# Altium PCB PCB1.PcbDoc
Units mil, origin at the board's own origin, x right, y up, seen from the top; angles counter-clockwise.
Board outline 3910.03 x 3525.03 mil, 2 copper layers (Top Layer, Bottom Layer); 80 components, 69 nets, 260 pads, 105 vias.
Unrouted connection lines stored in the file: 3.
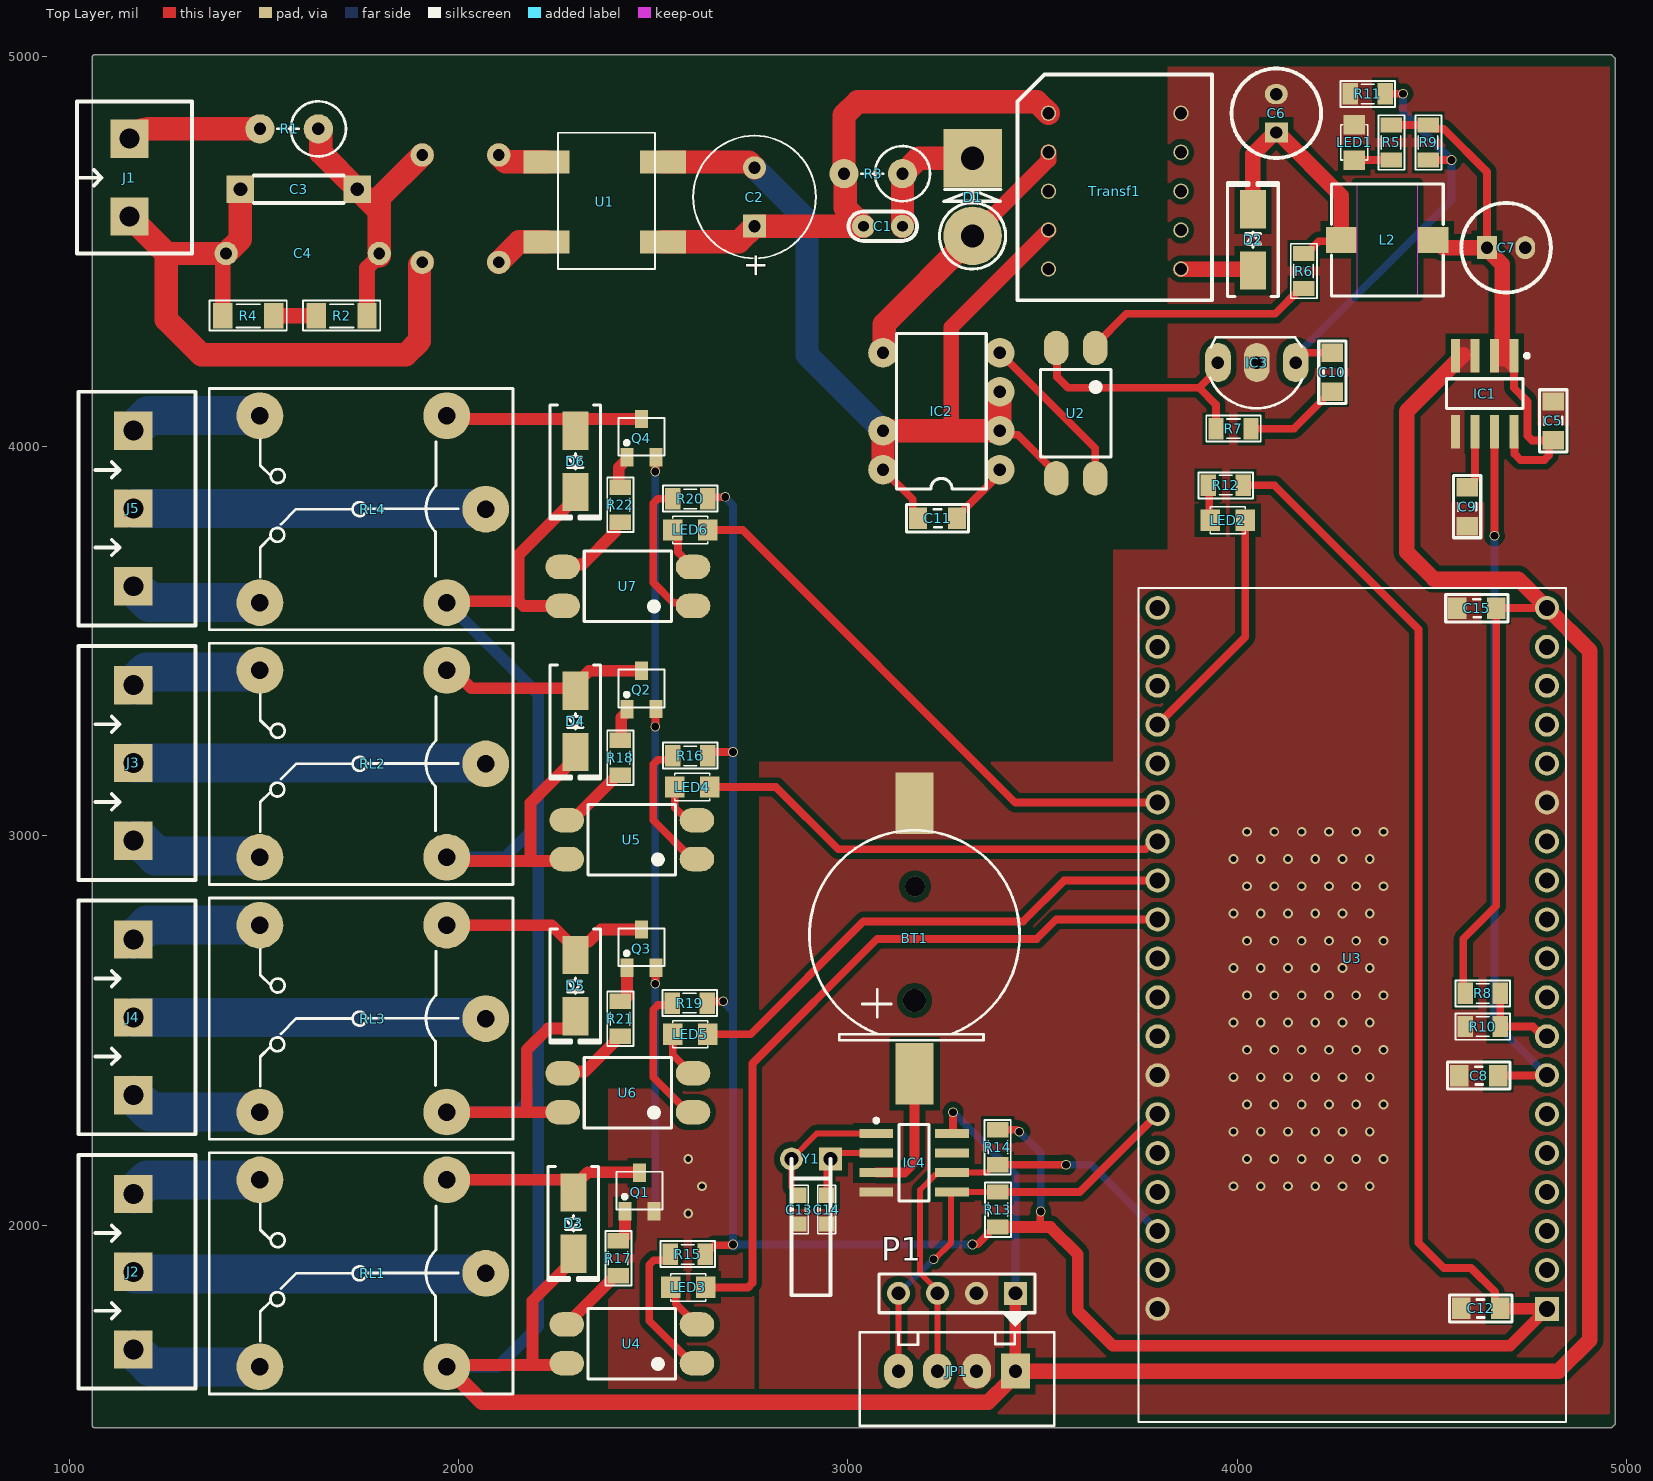
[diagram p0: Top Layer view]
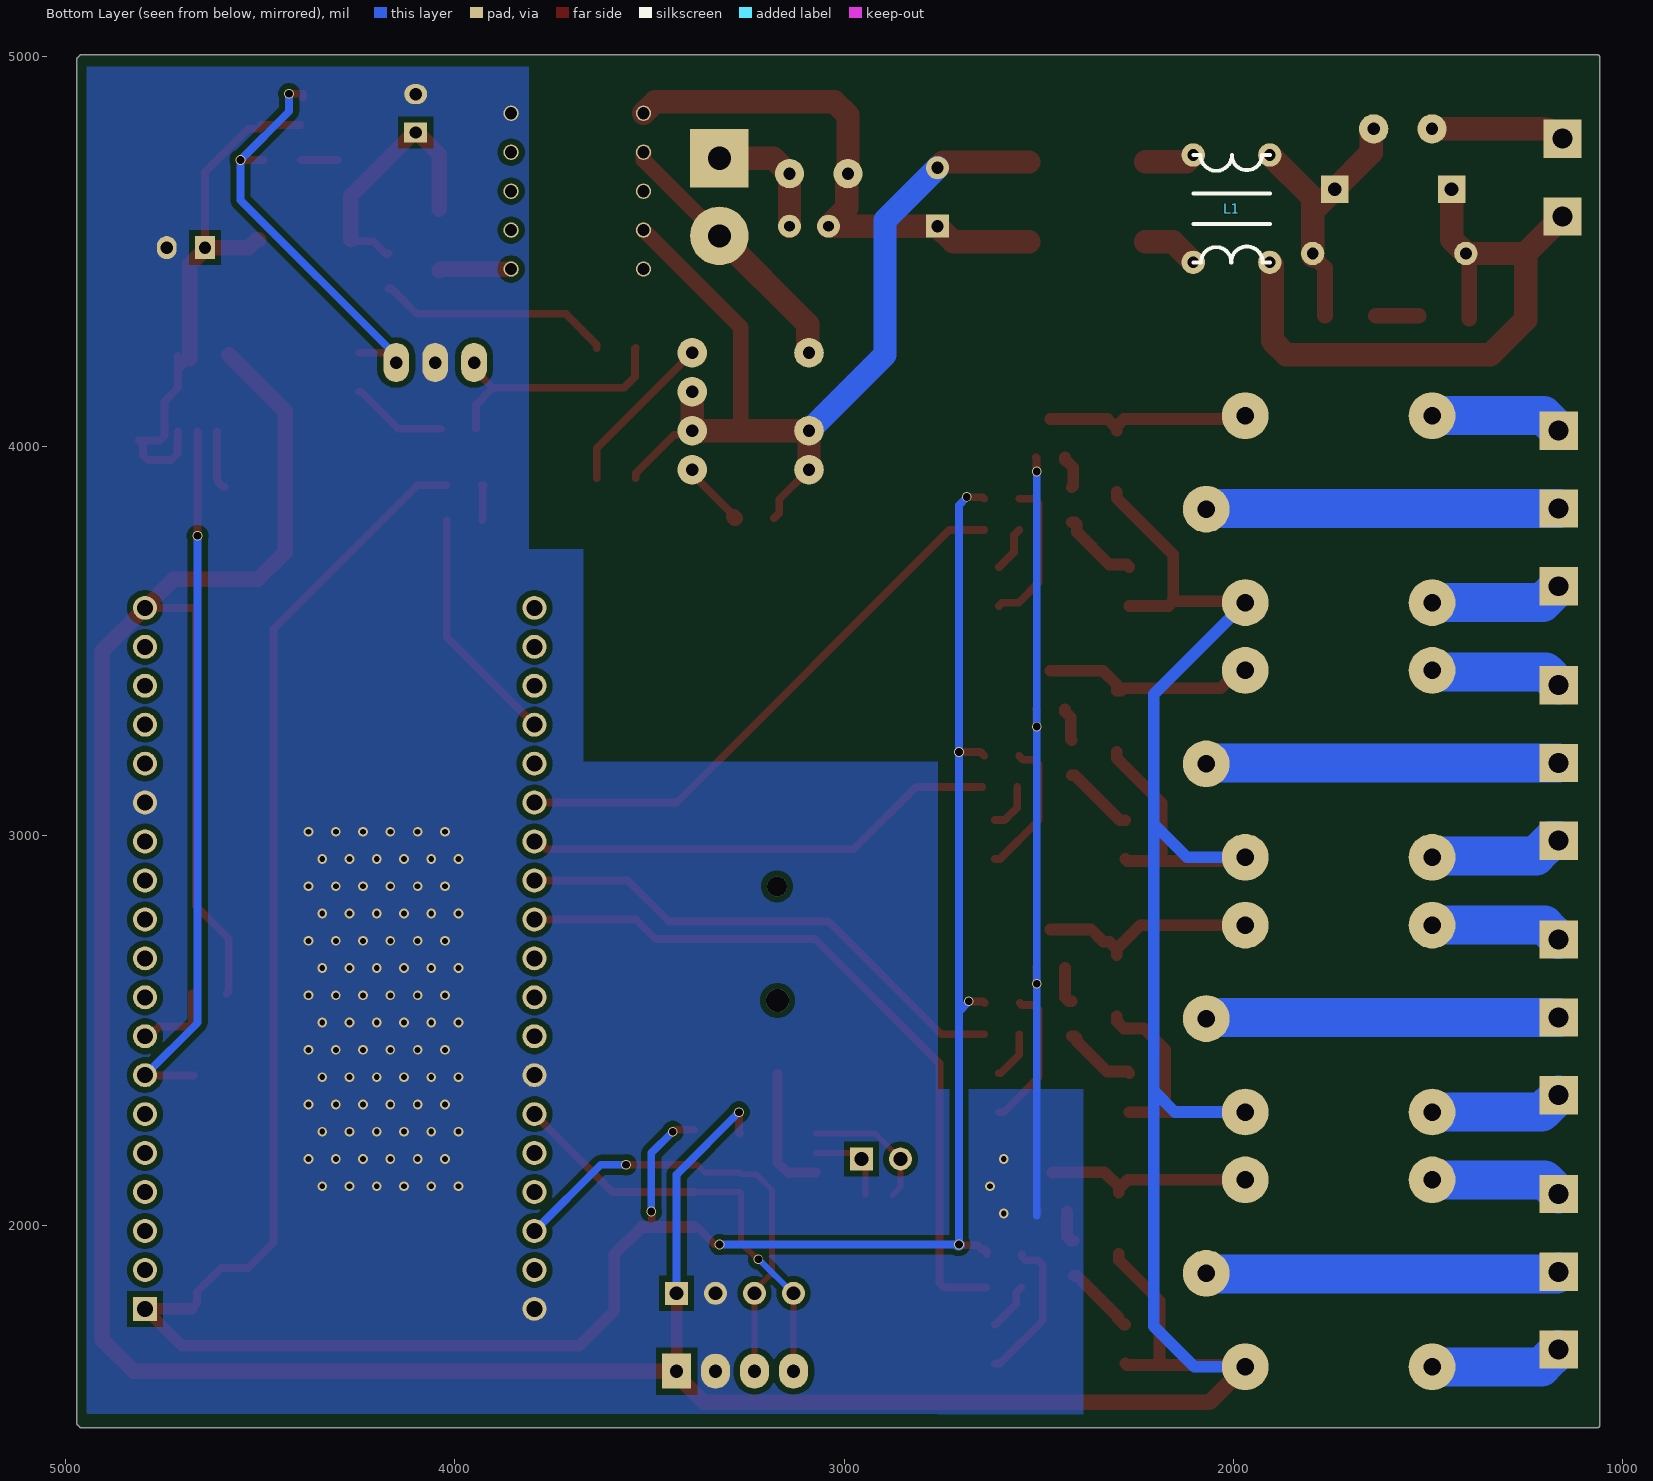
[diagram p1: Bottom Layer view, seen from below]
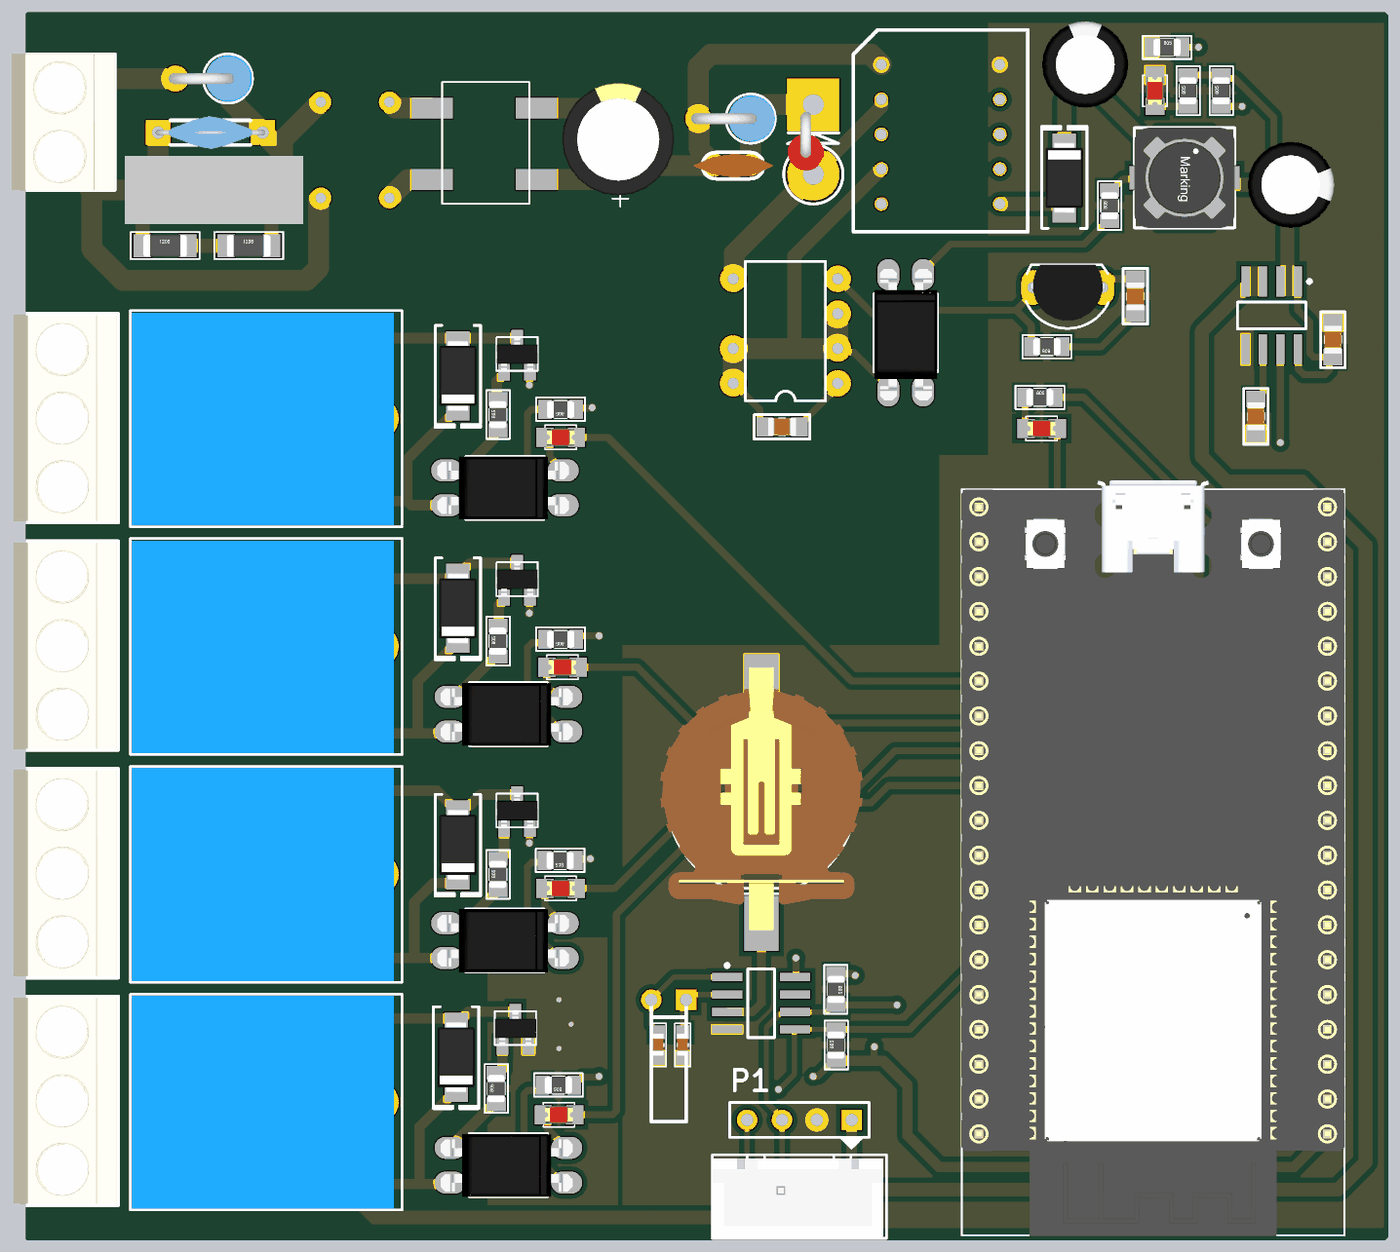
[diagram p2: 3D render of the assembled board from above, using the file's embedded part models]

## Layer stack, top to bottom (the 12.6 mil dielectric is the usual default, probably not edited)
Top Solder: solder mask 0.4, Solder Resist, Dk 3.5
Top Layer: signal copper 1.4
Dielectric 1: dielectric 12.6, FR-4, Dk 4.8
Bottom Layer: signal copper 1.4
Bottom Solder: solder mask 0.4, Solder Resist, Dk 3.5

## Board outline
1059.98,1485 1059.98,5000 cw(c1065,5000) 1061.45,5003.55 cw(c1065,5000) 1065.03,5005.01 4959.14,5005.01 cw(c4959.14,5000) 4962.71,5003.53 4968.55,4997.69 cw(c4965.03,4994.15) 4970.02,4994.14 4970.02,1490.86 cw(c4965,1490.86) 4968.53,1487.29 4962.69,1481.45 cw(c4959.15,1484.97) 4959.14,1479.98 1065,1479.98 cw(c1065,1485)

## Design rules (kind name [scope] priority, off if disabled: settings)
Clearance [All] p1: gap=15 ignorepadtopadclearanceinfootprint=FALSE
PolygonConnect [All] p1: connectstyle=Direct reliefconductorwidth=10 reliefentries=4 polygonreliefangle="90 Angle" airgapwidth=10
RoutingVias [All] p1: holewidth=18 width=23 viastyle="Through Hole" minholewidth=15 minwidth=20 maxholewidth=40 maxwidth=50
SolderMaskExpansion [All] p1: expansion=4 istentingtop=FALSE
Width [All] p1: maxlimit=100 minlimit=12 preferedwidth=15
30 further rules are at their usual default settings.

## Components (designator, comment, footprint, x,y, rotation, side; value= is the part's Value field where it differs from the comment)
BT1 "Battery3.3V" "CR1220 SMD" 3180,2730 r0 top
C1 "10nF/500V" "tu gom" 3090,4565 r0 top
C2 "33uF" CA-ALU-8 2760,4640 r90 top value=104
C3 "14D471K" 103/2KV 1440,4660 r0 top
C4 "Cap AC filter" "Cap AC filter" 1600,4495 r0 top
C5 "100nF" CAP_0805 4810,4065 r90 top value=33p
C6 "330uF/16V" C8mm 4100,4855 r90 top
C7 "100uF" C8mm 4690,4510 r0 top
C8 "100nF" CAP_0805 4620,2385 r0 top value=33p
C9 "10nF" CAP_0805 4591,3845 r270 top value=33p
C10 "100nF" CAP_0805 4245,4190 r270 top value=33p
C11 "100nF" CAP_0805 3230,3816 r0 top value=33p
C12 "100nF" CAP_0805 4625,1785 r180 top value=33p
C13 "10pF" CAP_0603 2875,2040 r90 top value=33p
C14 "10pF" CAP_0603 2945,2040 r90 top value=33p
C15 "100nF" CAP_0805 4615,3585 r0 top value=33p
D1 "1N4937" D5AN 3320,4740 r270 top value=1N5408
D2 "SS34" "DIODE SMA" 4040,4530 r90 top
D3 "M7" "DIODE SMA" 2295,2005 r270 top
D4 "M7" "DIODE SMA" 2300,3293.74 r270 top
D5 "M7" "DIODE SMA" 2300,2615 r270 top
D6 "M7" "DIODE SMA" 2300,3961.26 r270 top
IC1 "Current Sensor IC" SOIC-8 4635,4135 r270 top
IC2 "TNY267" TNY264 3436.85,3873.46 r90 top
IC3 "TL431" qto-92 4050,4215 r180 top
IC4 "DS1307Z" SOIC-8 3170,2160 r0 top
J1 "KF2" KF2-5.08 1155,4690 r90 top
J2 "KF3" KF3-5.08 1165,2080 r270 top
J3 "KF3" KF3-5.08 1165,3386.67 r270 top
J4 "KF3" KF3-5.08 1165,2733.33 r270 top
J5 "KF3" KF3-5.08 1165,4040 r270 top
JP1 "JP4" CON4 3430,1625 r180 top value="Connector 4"
L1 "Inductor EE8.3" "Inductor EE8.3" 2005,4610 r270 bottom
L2 "3.3uH" L-SMD-M-7.3x4.5 4385,4530 r90 top value="150 mH"
LED1 "LED" LED-0805-Red 4300,4735 r90 top value="LED 3 ly Single Colour"
LED2 "LED" LED-0805-Red 3930,3810 r0 top value="LED 3 ly Single Colour"
LED3 "LED" LED-0805-Red 2545,1840 r0 top value="LED 3 ly Single Colour"
LED4 "LED" LED-0805-Red 2555,3125 r0 top value="LED 3 ly Single Colour"
LED5 "LED" LED-0805-Red 2550,2490 r0 top value="LED 3 ly Single Colour"
LED6 "LED" LED-0805-Red 2550,3785 r0 top value="LED 3 ly Single Colour"
P1 "Header 4" HDR1X4 3430,1825 r180 top
Q1 "2N222" SOT23D 2465,2085 r0 top value=C1815
Q2 "2N222" SOT23D 2470,3374.21 r0 top value=C1815
Q3 "2N222" SOT23D 2470,2710 r0 top value=C1815
Q4 "2N222" SOT23D 2470,4020.79 r0 top value=C1815
R1 "2R/2W" RES-1WD 1575,4815 r180 top value="R1/4W - 1K"
R2 "1M" RES-SMD-1206 1700,4335 r0 top
R3 "200k/2W" RES-1WD 3075,4700 r180 top value="R1/4W - 1K"
R4 "1M" RES-SMD-1206 1460,4335 r0 top
R5 "1k" RES-SMD-0805 4395,4780 r90 top
R6 "200R" RES-SMD-0805 4170,4450 r90 top
R7 "3.3k" RES-SMD-0805 3990,4045 r180 top
R8 "10k" RES-SMD-0805 4630,2595 r0 top
R9 "11k" RES-SMD-0805 4490,4780 r90 top
R10 "3k" RES-SMD-0805 4630,2510 r0 top
R11 "10k" RES-SMD-0805 4335,4905 r0 top
R12 "1k" RES-SMD-0805 3970,3900 r0 top
R13 "10k" RES-SMD-0805 3385,2040 r90 top
R14 "10k" RES-SMD-0805 3385,2200 r270 top
R15 "1k" RES-SMD-0805 2588.5,1925 r180 top
R16 "1k" RES-SMD-0805 2595,3205 r180 top
R17 "1k" RES-SMD-0805 2410,1915 r90 top
R18 "1k" RES-SMD-0805 2415,3200 r90 top
R19 "1k" RES-SMD-0805 2593.5,2570 r180 top
R20 "1k" RES-SMD-0805 2595,3865 r180 top
R21 "1k" RES-SMD-0805 2415,2530 r90 top
R22 "1k" RES-SMD-0805 2415,3850 r90 top
RL1 "Relay 10A/12V" "RELAY 5" 1745,1876.17 r180 top value="Relay SPDT, 10A, 12V"
RL2 "Relay 10A/12V" "RELAY 5" 1745,3184.39 r180 top value="Relay SPDT, 10A, 12V"
RL3 "Relay 10A/12V" "RELAY 5" 1745,2530.28 r180 top value="Relay SPDT, 10A, 12V"
RL4 "Relay 10A/12V" "RELAY 5" 1745,3838.5 r180 top value="Relay SPDT, 10A, 12V"
Transf1 "Transformer EE12.7" "Transformer EE12.7" 3685,4655 r270 top
U1 "Diode Bridge Flate" DB207S 2375,4625 r270 top
U2 "OPTO PC817 SMD" SOP4 3585,4085 r270 top value=PC817
U3 "ESP32-DEVKITC-32D" MODULE_ESP32-DEVKITC-32D 4295,2562.95 r180 top
U4 "OPTO PC817 SMD" SOP4 2445,1695 r180 top value=PC817
U5 "OPTO PC817 SMD" SOP4 2445,2990 r180 top value=PC817
U6 "OPTO PC817 SMD" SOP4 2435,2340 r180 top value=PC817
U7 "OPTO PC817 SMD" SOP4 2435,3640 r180 top value=PC817
Y1 "32.768KHz" XTAL32K 2955,2170 r180 top

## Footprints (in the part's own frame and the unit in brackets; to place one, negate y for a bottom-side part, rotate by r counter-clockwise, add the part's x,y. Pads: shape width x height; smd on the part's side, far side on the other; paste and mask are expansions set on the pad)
103/2KV [mm]
  rect 1.8x1.8 hole 0.9: 1(0,0) 2(7.62,0)
  silkscreen extent 0.89,-0.89 6.73,0.89, body extent -0.19,-1.2 7.81,1.19, height 9.03
C8mm [mm]
  rect 1.3x1.5 hole 0.8: 1(-1.25,0)
  oval 1.3x1.5 hole 0.8: 2(1.25,0)
  silkscreen extent -2.92,-2.92 2.92,2.92, body extent -3.15,-3.15 3.16,3.15, height 11.51
CA-ALU-8 [mm] "Polarized capacitors, Aluminum Electrolytic Capacitors, 2-Leads, Body 8x16x3.5x0.5"
  rect 1.5x1.5 hole 0.8: 1(-1.905,0)
  round 1.5 hole 0.8: 2(1.905,0)
  silkscreen extent -4,-4 4,4, body extent -4.1,-4.1 4.1,4.1, height 14.4
"Cap AC filter" [mil]
  round 60 hole 30: 1(-196.85,0) 2(196.85,0)
  body extent -256,-98 256,98, height 472
CAP_0603 [mm]
  rect 1x0.95 smd mask+0.076: 1(-0.94,0) 2(0.94,0)
  silkscreen extent -1.57,-0.58 1.57,0.58, body extent -0.77,-0.39 0.83,0.41, height 0.9
CAP_0805 [mm]
  rect 1.2x1.4 smd: 1(-1.27,-0.025) 2(1.27,-0.025)
  silkscreen extent -2.03,-0.91 2.03,0.86, body extent -1.01,-0.66 1.01,0.61, height 0.61
CON4 [mil] "CON4"
  rect 75x90 hole 34: 1(0,0)
  oval 75x90 hole 34: 2(100,0) 3(200,0) 4(300,0)
  silkscreen extent -100,-150 400,140, body extent -90,-90 398,136, height 276
"CR1220 SMD" [mil] "CR1220 SMD"
  rect 98.43x157.48 smd: 1(-9,-341) 2(-9,353)
  silkscreen extent -279,-255 261,284, body extent -299,-362 281,394, height 179
D5AN [mil] "Diode 5A, W 200mil, L 250mil"
  round 150 hole 60: 1(200,0)
  rect 150x150 hole 60: 2(0,0)
  silkscreen extent 81,-85 285,85, body extent 21,-74 189,31, height 252
DB207S [mm] "Bridge Rectifiers 2A 1000V"
  rect 1.5x3 smd: 1(2.54,3.81) 2(2.54,-3.785) 3(-2.667,-3.785) 4(-2.667,3.81)
  silkscreen extent -4.57,-3.05 4.32,3.3
"DIODE SMA" [mm] "SMA"
  rect 2.5x1.7 smd: 1(-2,0) 2(2,0)
  silkscreen extent -3.68,-1.65 3.75,1.65, body extent -2.6,-1.37 2.6,1.37, height 2.4
HDR1X4 [mm] "Connector; Header; 4 Position"
  rect 1.5x1.5 hole 0.9: 1(0,0)
  round 1.5 hole 0.9: 2(2.54,0) 3(5.08,0) 4(7.62,0)
  silkscreen extent -1.27,-1.27 8.89,1.27
"Inductor EE8.3" [mil]
  round 60 hole 30: 1(-137.8,98.43) 2(-137.8,-98.43) 3(137.8,98.43) 4(137.8,-98.43)
  silkscreen extent -138,-98 138,98
KF2-5.08 [mm]
  rect 2.5x2.5 hole 1.3: 1(-2.54,0) 2(2.54,0)
  silkscreen extent -4.95,-4.08 4.95,3.43, body extent -5,-4.07 5,3.43, height 10
KF3-5.08 [mm]
  rect 2.5x2.5 hole 1.3: 1(0,0) 2(5.08,0) 3(10.147,0)
  silkscreen extent -2.54,-3.58 12.7,4.06, body extent -2.42,-3.51 12.58,3.99, height 10
L-SMD-M-7.3x4.5 [mm] "WE-PDA SMD Shielded Power Inductor, 7345"
  rect 1.7x2 smd: 1(0,3) 2(0,-3)
  Top Layer keep-out region: -3.65,-2 3.65,-2 3.65,2 -3.65,2
  silkscreen extent -3.65,-3.65 3.65,3.65, body extent -3.65,-3.65 3.65,3.65, height 4.05
LED-0805-Red [mil]
  rect 50x55 smd: 1(0,0) 2(90,0)
  silkscreen extent 0,-35 90,35, body extent 5,-25 85,25, height 43
MODULE_ESP32-DEVKITC-32D [mm]
  rect 1.56x1.56 hole 1.04: 1(-12.7,19.76)
  round 1.56 hole 1.04: 2(-12.7,17.22) 3(-12.7,14.68) 4(-12.7,12.14) 5(-12.7,9.6) 6(-12.7,7.06) 7(-12.7,4.52) 8(-12.7,1.98) 9(-12.7,-0.56) 10(-12.7,-3.1) 11(-12.7,-5.64) 12(-12.7,-8.18) 13(-12.7,-10.72) 14(-12.7,-13.26) 15(-12.7,-15.8) 16(-12.7,-18.34) 17(-12.7,-20.88) 18(-12.7,-23.42) 19(-12.7,-25.96) 20(12.7,19.76) 21(12.7,17.22) 22(12.7,14.68) 23(12.7,12.14) 24(12.7,9.6) 25(12.7,7.06) 26(12.7,4.52) 27(12.7,1.98) 28(12.7,-0.56) 29(12.7,-3.1) 30(12.7,-5.64) 31(12.7,-8.18) 32(12.7,-10.72) 33(12.7,-13.26) 34(12.7,-15.8) 35(12.7,-18.34) 36(12.7,-20.88) 37(12.7,-23.42) 38(12.7,-25.96)
  silkscreen extent -13.95,-27.25 13.95,27.15, body extent -13.97,-27.9 13.97,27.2, height 8.25
qto-92 [mil] "TO-92"
  oval 66x100 hole 32: 1(-100,0) 2(0,0) 3(100,0)
  silkscreen extent -117,-65 120,118, body extent -109,-66 109,95, height 245
"RELAY 5" [mil] "Reley DPDT, 8 pin, 1A, W400mil, L800mil,H 300mil"
  round 120 hole 45: 1(-325,0) 2(255,240) 3(255,-240) 4(-225,-240) 5(-225,240)
  silkscreen extent -395,-310 385,310, body extent -371,-304 381,306, height 602
RES-1WD [mil]
  round 75 hole 31.5: 1(-65,0) 2(85,0)
  silkscreen extent -136,-71 40,71, body extent -135,-67 105,67, height 498
RES-SMD-0805 [mil]
  rect 39.37x55 smd: 1(-45,0) 2(45,0)
  silkscreen extent -70,-34 70,33, body extent -39,-25 39,25, height 31
RES-SMD-1206 [mil]
  rect 50x65 smd: 1(-65,0) 2(65,0)
  silkscreen extent -99,-38 99,39, body extent -63,-31 63,32, height 40
SOIC-8 [mm] "SOIC, 8-Leads, Body 5,0x4,0mm (max), Pitch 1,27mm, IPC Medium Density"
  rect 2.2x0.6 smd: 1(-2.475,1.905) 2(-2.475,0.635) 3(-2.475,-0.635) 4(-2.475,-1.905) 5(2.475,-1.905) 6(2.475,-0.635) 7(2.475,0.635) 8(2.475,1.905)
  silkscreen extent -2.6,-2.5 0.98,2.88, body extent -3.2,-2.5 3.2,2.5, height 1.75
SOP4 [mm]
  oval 2.25x1.6 smd: 1(-4.25,1.27) 2(-4.25,-1.27) 3(4.25,-1.27) 4(4.25,1.27)
  silkscreen extent -2.85,-2.3 2.85,2.3, body extent -4.67,-2.29 4.93,2.31, height 3.6
SOT23D [mm] "SOT 23C - 1-3-2 - BCE"
  rect 0.85x1.2 smd: 1(-0.95,-1.25) 2(0.94,-1.245) 3(0,1.25)
  silkscreen extent -1.5,-1.14 1.5,1.32, body extent -1.5,-1.17 1.5,1.33, height 1.06
TNY264 [mil] "Opto"
  round 76 hole 32: 1(66.54,46.85) 2(166.54,46.85) 3(266.54,46.85) 4(366.54,46.85) 5(366.54,346.85) 7(166.54,346.85) 8(66.54,346.85)
  silkscreen extent 17,82 417,312
"Transformer EE12.7" [mm]
  round 1 hole 0.8: 1(-5.08,-4.318) 2(-2.54,-4.318) 3(0,-4.318) 4(2.54,-4.318) 5(5.08,-4.318) 6(5.08,4.318) 7(2.54,4.318) 8(0,4.318) 9(-2.54,4.318) 10(-5.08,4.318)
  silkscreen extent -7.62,-6.35 7.11,6.35
"tu gom" [mm] "Tu gom mini"
  round 1.5 hole 0.7: 1(-1.27,0) 2(1.27,0)
  silkscreen extent -2.25,-0.97 2.22,0.97, body extent -2.92,-0.85 2.92,0.85, height 6.12
XTAL32K [mm] "Connector; Header; 2 Position"
  rect 1.5x1.5 hole 0.9: 1(0,0)
  round 1.5 hole 0.9: 2(2.54,0)
  silkscreen extent 0,0 2.54,8.89

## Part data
BT1: "Multicell Battery"
C1: library part "Tu gom 103 50V", "Tụ gốm 103 10nF 500V"
C2: library part CAP-ALU-DIP, "Capacitor (Semiconductor SIM Model)"
C3: library part Cap2KV, "Capacitor Ceramic 2KV"
C4: "Tụ lọc nguồn AC 0.1uf 275v 10mm"
C5 C8 C9 C10 C11 C12 C13 C14 C15: library part CapSMD, "Capacitor"
C6 C7: library part "Cap Pol", "Polarized Capacitor (Axial)"
D1: library part D5A, "Diode 5A"
D2: library part "Diode SS34 ( 1N5822 )", "Dán"
D3 D4 D5 D6: library part "Diode M7 ( 4007 )", "Dán"
IC1: library part ACS712
IC2: library part TNY264, "IC Power"
IC3: "Programmable Shunt Regulator"
IC4: "0x68"
J1: Manufacturer="Würth Elektronik eiSos GmbH", partNo=691103110002
J2 J3 J4 J5: Manufacturer="Würth Elektronik eiSos GmbH", partNo=691103110003
JP1: library part Con4, "Connector 4"
L2: library part L-DIP-1, "Inductor"
LED1 LED2 LED3 LED4 LED5 LED6: "LED Single colour Green and Red"
P1: "Header, 4-Pin"
Q1 Q2 Q3 Q4: "NPN 600mW, ECB"
R1 R3: library part "Resistor - DIP", "Resistor - DIP"
R2 R4 R5 R6 R7 R8 R9 R10 R11 R12 R13 R14 R15 R16 R17 R18 R19 R20 R21 R22: library part "Resistor - SMD", "Resistor", Manufacturer="Generic Components"
RL1 RL2 RL3 RL4: library part "Relay 5", "Relay SPDT,10A - 12VDC 5 Pin"
Transf1: library part "Tranformer EE16"
U1: "Diode Bridge"
U2 U4 U5 U6 U7: "Single Opto"
U3: "EVAL BOARD FOR ESP-WROOM-32", Package=None
Y1: library part XTAL/32KHz, "Crystal Oscillator"

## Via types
v1: diameter 25, hole 15, Top Layer to Bottom Layer, tented both sides, 86 vias
v2: diameter 25, hole 20, Top Layer to Bottom Layer, tented both sides, 16 vias
v3: diameter 25, hole 15, Top Layer to Bottom Layer, tented top, 1 vias
v4: diameter 59.06, hole 59.06, Top Layer to Bottom Layer, tented both sides, 1 vias
v5: diameter 51.18, hole 51.18, Top Layer to Bottom Layer, tented both sides, 1 vias

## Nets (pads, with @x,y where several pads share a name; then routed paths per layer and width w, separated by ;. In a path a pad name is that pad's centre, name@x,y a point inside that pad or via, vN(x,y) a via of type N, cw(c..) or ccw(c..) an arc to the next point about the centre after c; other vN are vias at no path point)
+3V3: C12.1 R12.2 R13.1 R14.1 R15.1 R16.1 R19.1 R20.1 U3.1 | length 7487
  Top Layer w20: R15.1 2633.5,1932.81 2638.19,1937.5 2646,1937.5 2656.59,1948.09 2703.09,1948.09 v2(2705,1950) ; R19.1 2642.55,2574.04 2679.04,2574.04 v2(2680,2575) ; R16.1 2640,3205.31 2649.69,3215 v2(2705,3215) ; R20.1 2644.05,3869.04 2684.04,3869.04 v2(2685,3870) ; v2(3319.59,1950) 3320.54,1950.96 3333.14,1950.96 3377.19,1995 R13.1 ; R14.1 3433.65,2245 3438.65,2240 v2(3440,2240) ; 3493.02,1995 3494.04,1996.02 3494.04,2034.04 v2(3495,2035) ; R12.2@4020,3900 4095,3900 4465,3530 4465,1955 4530,1890 4600,1890 4661.38,1828.62 4661.38,1799.62 C12.1
  Top Layer w30: R13.1 3493.02,1995 3520,1995 3590,1925 3590,1780 3680,1690 4700,1690 U3.1 4794.5,1785.5 4675.5,1785.5 C12.1
  Bottom Layer w20: v2(2680,2575) 2680,2573.65 2705,2548.65 ; v2(2685,3870) 2685,3868.65 2705,3848.65 v2(2705,3215) 2705,2548.65 ; v2(2705,1950) 2705,2548.65 ; v2@2707.31,1950 v2(3319.59,1950) ; v2(3440,2240) 3495,2185 v2(3495,2035)
  Bottom Layer w30: v2(2705,1950) v2@2707.31,1950
+5: C15.2 D3.2 D4.2 D5.2 D6.2 IC1.3 IC1.4 IC4.8 JP1.1 P1.1 R8.1 RL1.5 RL2.5 RL3.5 RL4.5 U3.19 U4.4 U5.4 U6.4 U7.4 | length 13217.1
  Top Layer w20: IC4.8 3268.19,2235 3270,2236.81 v2(3270,2290) ; R8.1 4580,2600 4580,2735 4665,2820 C15.2 4665.5,3584.5 4794.5,3584.5 U3.19
  Top Layer w30: RL1.5 1974.42,1640.58 2190,1640.58 ; RL3.5 1970.08,2290.2 2175,2290.2 ; RL2.5 1979.39,2935 2180,2935 ; RL4.5 1973.22,3601.72 2155,3601.72 ; 2187.37,2290.2 2175,2290.2 ; 2187.57,2290 U6.4 ; U7.4 2166.72,3590 2155,3601.72 ; U4.4 2273.26,1640.58 2190,1640.58 ; U5.4 2272.68,2935 2180,2935 ; D3.2 2295,1910.51 2190,1805.51 2190,1640.58 ; D5.2 2300,2523.46 2281.54,2505 2230,2505 2175,2450 2175,2290.2 ; D4.2 2300,3199.25 2185,3084.25 2185,2940 2180,2935 ; D6.2 2300,3866.77 2155,3721.77 2155,3601.72 ; JP1.1 P1.1
  Top Layer w40: RL1.5 2061.17,1545 3360.03,1545 3412.5,1597.47 3412.5,1607.5 JP1.1 4825,1625 4905,1705 4905,3475 U3.19 4721.24,3658.76 4504.67,3658.76 4435,3728.43 4435,3880 4435,4090 4580,4235
  Bottom Layer w20: v2(3270,2290) 3430,2130 P1.1
  Bottom Layer w30: RL1.5 2101.17,1636.17 2205,1740 2205,2345 ; RL3.5 2150.28,2290.28 2205,2345 ; RL2.5 2119.39,2944.39 2205,3030 ; RL4.5 2205,3363.5 2205,3030 ; 2205,2345 2205,3030
ESP_SCL: IC4.6 JP1.3 P1.3 R14.2 U3.22 | length 1191
  Top Layer w15: JP1.3 P1.3 3230,1832.21 3185,1877.21 3185,2090 3225.69,2130.69 3263.13,2130.69 IC4.6 3357.18,2135 3377.19,2155 R14.2
  Top Layer w20: R14.2 v2(3560,2155)
  Bottom Layer w20: v2(3560,2155) 3625,2155 U3.22
ESP_SDA: IC4.5 JP1.4 P1.4 R13.2 U3.25 | length 1130.3
  Top Layer w12: IC4.5@3265,2082.56 IC4.5
  Top Layer w15: JP1.4 P1.4 ; v2(3220,1912.5) 3222.5,1912.5 3265,1955 IC4.5@3265,2082.56 ; IC4.5 R13.2
  Top Layer w20: R13.2 3595,2085 U3.25
  Bottom Layer w15: P1.4 3131.25,1825 3218.75,1912.5 v2(3220,1912.5)
GND_AC: C2.2 C11.1 IC2.2 IC2.3 IC2.7 IC2.8 Transf1.4 U1.4 U2.3 | length 2544
  Top Layer w20: IC2.8 3166.38,3863.62 3166.38,3828.62 C11.1 ; IC2.2 3400.72,4029.28 3436.19,4029.28 3535,3930.47 U2.3
  Top Layer w40: 3265,4040 3265,4305 Transf1.4 ; IC2.3@3385,4145 IC2.3
  Top Layer w60: U1.4 2745,4730 C2.2 ; IC2.8 IC2.7 3265,4040 IC2.2 IC2.3
  Bottom Layer w60: C2.2 2895,4580 2895,4235 IC2.7
GND_DC: BT1.2 C5.2 C6.2 C7.2 C8.1 C9.2 C12.2 C13.1 C14.1 C15.1 IC1.5 IC3.2 IC4.4 JP1.2 LED1.2 P1.2 Q1.2 Q2.2 Q3.2 Q4.2 R10.1 R11.1 Transf1.10 U3.14 U3.20 U3.26 | length 2038.4
  Top Layer w20: Q1.2 Q1.2@2504.04,2033.96 ; v2(2505,2620) 2505.96,2620.96 2505.96,2659.96 Q3.2 ; v2(2505,3280) 2505.96,3280.96 2505.96,3324.17 Q2.2 ; v2(2505,3935) 2505.96,3935.96 2505.96,3970.74 Q4.2
  Bottom Layer w20: 2505,2025 v2(2505,2620) v2(2505,3280) v2(2505,3935)
  other v1: 2590,2030 3990,2100 4060,2100 4130,2100 4200,2100 4270,2100 4340,2100 2590,2170 4025,2170 4095,2170 4165,2170 4235,2170 4305,2170 4375,2170 3990,2240 4060,2240 4130,2240 4200,2240 4270,2240 4340,2240 4025,2310 4095,2310 4165,2310 4235,2310 4305,2310 4375,2310 3990,2380 4060,2380 4130,2380 4200,2380 4270,2380 4340,2380 4025,2450 4095,2450 4165,2450 4235,2450 4305,2450 4375,2450 3990,2520 4060,2520 4130,2520 4200,2520 4270,2520 4340,2520 4025,2590 4095,2590 4165,2590 4235,2590 4305,2590 4375,2590 3990,2660 4060,2660 4130,2660 4200,2660 4270,2660 4340,2660 4025,2730 4095,2730 4165,2730 4235,2730 4305,2730 4375,2730 3990,2800 4060,2800 4130,2800 4200,2800 4270,2800 4340,2800 4025,2870 4095,2870 4165,2870 4235,2870 4305,2870 4375,2870 3990,2940 4060,2940 4130,2940 4200,2940 4270,2940 4340,2940 4025,3010 4095,3010 4165,3010 4235,3010 4305,3010 4375,3010
  other v3: 2625,2100
I_MEASURE: C8.2 IC1.7 U3.7 | length 1833.9
  Top Layer w20: v2(4660,3770) IC1.7 ; C8.2 4670.5,2384.5 4794.5,2384.5 U3.7
  Bottom Layer w20: v2(4660,3770) 4660,2520 U3.7
NetBT1_1: BT1.1 IC4.3 | length 337.2
  Top Layer w25: IC4.3 3145,2135 3171,2161 BT1.1
NetC1_1: C1.1 C2.1 R3.2 Transf1.1 U1.1 | length 1389.1
  Top Layer w60: U1.1 2720,4525 C2.1 C1.1 2992.87,4612.13 2992.87,4697.13 R3.2 2990,4849.85 3025.15,4885 3485,4885 Transf1.1
NetC1_2: C1.2 D1.2 R3.1 | length 331.6
  Top Layer w60: C1.2 R3.1 3142.08,4700 3182.08,4740 D1.2
NetC3_1: C3.1 C4.1 J1.1 L1.3 R4.1 | length 1713.7
  Top Layer w40: R4.1@1395,4327.5 R4.1 1395,4470.8 cw(c1435,4470.8) C4.1
  Top Layer w60: J1.1 1250,4495 ; C3.1 1440,4531.85 C4.1 1250,4495 ; L1.3 1900,4465.63 1900,4270.15 1864.85,4235 1340,4235 1250,4325 1250,4495
NetC3_2: C3.2 C4.2 L1.1 R1.1 R2.2 | length 748.3
  Top Layer w40: R2.2 1765,4457.74 C4.2@1796.85,4489.59
  Top Layer w60: R1.1 1646.7,4808.3 1646.7,4753.3 C3.2 1796.85,4603.15 ; C4.2@1796.85,4489.59 C4.2 1796.85,4603.15 ; L1.1 1796.85,4638.07 1796.85,4603.15
NetC5_1: C5.1 C7.1 IC1.1 IC1.2 IC1.8 L2.2 R5.2 R9.2 | length 1479
  Top Layer w20: R5.2 R9.2@4497.81,4825 ; R9.2 4499.69,4815.31 4529.69,4815.31 4640.79,4704.21 C7.1 ; 4680,4225 IC1.1@4710,4195 ; IC1.8 4710,4016.81 4711.81,4015 4711.81,3979.9 4726.72,3965 4788.28,3965 4800,3976.72 4800,4004 C5.1 4756.72,4015 4745,4026.72 4745,4115 4710,4150 IC1.1@4710,4195 ; IC1.1 IC1.1@4710,4195
  Top Layer w40: L2.2 4509.02,4530 4529.02,4510 C7.1 4640.79,4506.06 4680,4466.85 4680,4225
NetC6_1: C6.1 D2.2 L2.1 R6.2 | length 682.8
  Top Layer w20: R6.2 4177.81,4495 4209.24,4526.42 4263.31,4526.42 L2.1
  Top Layer w40: D2.2 4040,4749.72 4096.06,4805.79 C6.1 4103.94,4805.79 4266.89,4642.83 L2.1
NetC9_1: C9.1 IC1.6 | length 153.1
  Top Layer w20: C9.1 4593.94,3895 4607.56,3908.62 4607.56,3912.56 4610,3915 IC1.6
NetC10_1: C10.1 IC3.1 R9.1 R11.2 | length 1119.3
  Top Layer w20: IC3.1 4150,4218.75 4171.25,4240 C10.1 ; R11.2@4389.69,4895 4389.69,4905 v2(4425,4905) ; R9.1 v2(4550,4735)
  Bottom Layer w20: IC3.1 4150,4232 4550,4632 v2(4550,4735) 4425,4860 v2(4425,4905)
NetC10_2: C10.2 R7.1 | length 248.3
  Top Layer w20: R7.1 4145.06,4045 4240.06,4140 C10.2
NetC11_2: C11.2 IC2.1 | length 175.7
  Top Layer w20: C11.2 3280,3818.94 3390,3928.94 IC2.1
  Top Layer w40: C11.2 C11.2@3283.62,3818.62
NetC13_2: C13.2 IC4.1 Y1.2 | length 345.8
  Top Layer w15: C13.2 2875,2077.98 2855,2097.98 Y1.2 2920,2235 IC4.1
NetC14_2: C14.2 IC4.2 Y1.1 | length 220.9
  Top Layer w15: C14.2 2945,2160 Y1.1 2970,2185 IC4.2
NetD1_1: D1.1 IC2.5 Transf1.2 | length 691
  Top Layer w40: D1.1 3515,4735 Transf1.2
  Top Layer w60: IC2.5 3093.06,4243.06 3093.06,4313.06 D1.1
NetD2_1: D2.1 Transf1.6 | length 186.5
  Top Layer w40: Transf1.6 4036.26,4455 D2.1
NetD3_1: D3.1 Q1.3 RL1.4 | length 536.4
  Top Layer w30: RL1.4 2271.54,2116.17 D3.1@2295,2092.7 ; D3.1 2295,2099.49 2331.5,2135.99 2463.27,2135.99 Q1.3@2465,2134.26
NetD4_1: D4.1 Q2.3 RL2.4 | length 551.8
  Top Layer w30: RL2.4 1986.96,3424.39 2032.57,3378.78 2281.54,3378.78 2287.83,3372.48 D4.1 2300,3388.23 2335.2,3423.43 Q2.3
NetD5_1: D5.1 Q3.3 RL3.4 | length 561.5
  Top Layer w30: RL3.4 2239.21,2770.28 D5.1@2300,2709.49 ; D5.1 D5.1@2300,2709.49 ; Q3.3 2365.47,2759.21 2334.21,2727.95 2318.46,2727.95 D5.1@2300,2709.49
NetD6_1: D6.1 Q4.3 RL4.4 | length 532.4
  Top Layer w30: RL4.4 1978.5,4070 2281.54,4070 2300,4051.54 D6.1 ; D6.1@2300,4046.54 2323.46,4070 Q4.3
NetIC2_4: IC2.4 U2.4 | length 423.8
  Top Layer w20: IC2.4 3635,3995 U2.4
NetIC3_3: IC3.3 R7.2 U2.2 | length 659.4
  Top Layer w20: U2.2 3536.97,4250.35 3536.97,4178.03 3565,4150 3902,4150 ; R7.2 3945,4107 3902,4150 ; IC3.3 3950,4198 3902,4150
NetJ1_2: J1.2 R1.2 | length 342.8
  Top Layer w60: J1.2 1162.43,4797.43 cw(c1204.85,4755) 1204.85,4815 1485.94,4815 R1.2
NetJ2_1: J2.1 RL1.3 | length 340
  Bottom Layer w100: J2.1 1201.17,2116.17 RL1.3
NetJ2_2: J2.2 RL1.1 | length 907.6
  Bottom Layer w100: J2.2 1170,1875 2068.83,1875 RL1.1
NetJ2_3: J2.3 RL1.2 | length 343.4
  Bottom Layer w100: J2.3 1209.33,1636.17 RL1.2
NetJ3_1: J3.1 RL2.3 | length 340.6
  Bottom Layer w100: J3.1 1198.9,3420.56 1486.17,3420.56 RL2.3
NetJ3_2: J3.2 RL2.1 | length 907.6
  Bottom Layer w60: J3.2 J3.2@1166.14,3185.53
  Bottom Layer w100: J3.2 2067.72,3186.67 RL2.1
NetJ3_3: J3.3 RL2.2 | length 342.7
  Bottom Layer w100: J3.3 1184.63,2987.17 1223.58,2948.22 1486.17,2948.22 RL2.2
NetJ4_1: J4.1 RL3.3 | length 340.3
  Bottom Layer w100: J4.1 1201.94,2770.28 RL3.3
NetJ4_2: J4.2 RL3.1 | length 906.3
  Bottom Layer w100: J4.2 2066.94,2533.33 RL3.1
NetJ4_3: J4.3 RL3.2 | length 343
  Bottom Layer w100: J4.3 1208.56,2290.28 RL3.2
NetJ5_1: J5.1 RL4.3 | length 340.9
  Bottom Layer w100: J5.1 1203.5,4078.5 RL4.3
NetJ5_2: J5.2 RL4.1 | length 906.7
  Bottom Layer w60: J5.2 J5.2@1165.75,3839.25
  Bottom Layer w100: J5.2 2068.5,3840 RL4.1
NetJ5_3: J5.3 RL4.2 | length 342.4
  Bottom Layer w100: J5.3 1207,3598.5 RL4.2
NetL1_2: L1.2 U1.3 | length 138.5
  Top Layer w40: L1.2 L1.2@2109.5,4741.72
  Top Layer w60: L1.2 2120.75,4730.47 2225.53,4730.47 U1.3
NetL1_4: L1.4 U1.2 | length 144.4
  Top Layer w60: L1.4 2156.22,4525 U1.2
NetLED1_1: LED1.1 R5.1 | length 95
  Top Layer w20: LED1.1 R5.1
NetLED2_1: LED2.1 R12.1 | length 92.1
  Top Layer w20: R12.1 3927.5,3897.5 3927.5,3812.5 LED2.1
NetLED3_1: LED3.1 U4.2 | length 123.6
  Top Layer w20: LED3.1 2558.04,1826.96 2558.04,1798.12 2611.16,1745 U4.2
NetLED4_1: LED4.1 U5.2 | length 123.7
  Top Layer w20: LED4.1 2555,3071.72 2566.72,3060 2567.89,3060 2587.89,3040 U5.2
NetLED5_1: LED5.1 U6.2 | length 124.5
  Top Layer w20: LED5.1 2550,2437.44 2597.44,2390 U6.2
NetLED6_1: LED6.1 U7.2 | length 117.4
  Top Layer w20: LED6.1 2563.66,3771.34 2563.66,3727.5 2601.16,3690 U7.2
NetQ1_1: Q1.1 R17.2 | length 87.7
  Top Layer w30: R17.2 2417.81,1960 2427.6,1969.78 Q1.1
NetQ2_1: Q2.1 R18.2 | length 87.3
  Top Layer w30: R18.2 2417.88,3247.88 2417.88,3303.39 2432.6,3318.11 Q2.1
NetQ3_1: Q3.1 R21.2 | length 97.7
  Top Layer w30: R21.2 2422.81,2575 2432.6,2584.78 Q3.1
NetQ4_1: Q4.1 R22.2 | length 88.2
  Top Layer w30: R22.2 2411.21,3898.79 2411.21,3945.38 2428.79,3962.95 2430.87,3962.95 2432.6,3964.68 Q4.1
NetR2_1: R2.1 R4.2 | length 110
  Top Layer w40: R4.2 R2.1
NetR6_1: R6.1 U2.1 | length 602.7
  Top Layer w20: U2.1 3635,4260 3715,4340 4097.19,4340 4162.19,4405 R6.1
NetR15_2: R15.2 U4.1 | length 379.1
  Top Layer w20: R15.2 2543.5,1919.69 2533.82,1910 2501.72,1910 2490,1898.28 2490,1754.53 2599.53,1645 U4.1
NetR16_2: R16.2 U5.1 | length 356.5
  Top Layer w20: R16.2 2550,3204.69 2540.32,3195 2511.72,3195 2500,3183.28 2500,3039.53 2599.53,2940 U5.1
NetR17_1: R17.1 U4.3 | length 186.7
  Top Layer w30: U4.3 2281.54,1745 2296.79,1760.24 2296.79,1764.6 2402.19,1870 R17.1
NetR18_1: R18.1 U5.3 | length 185
  Top Layer w30: U5.3 2292.19,3040 2407.19,3155 R18.1
NetR19_2: R19.2 U6.1 | length 368.6
  Top Layer w20: R19.2 2543.5,2565 2511.72,2565 2500,2553.28 2500,2379.53 2589.53,2290 U6.1
NetR20_2: R20.2 U7.1 | length 385.3
  Top Layer w20: R20.2 2511.72,3865 2500,3853.28 2500,3650 2551.77,3598.23 2594.1,3598.23 U7.1
NetR21_1: R21.1 U6.3 | length 191.3
  Top Layer w30: U6.3 2272,2394.33 2324.33,2394.33 2402.5,2472.5 2402.5,2480.31 2407.19,2485 R21.1
NetR22_1: R22.1 U7.3 | length 206.9
  Top Layer w30: U7.3 2273.99,3696.31 2318.82,3696.31 2402.5,3779.99 2402.5,3800.31 2407.19,3805 R22.1
RL1: LED3.2 U3.30 | length 1881.4
  Top Layer w20: LED3.2 2743.28,1840 2755,1851.72 2755,2415 3075,2735 3485,2735 3535,2785 U3.30
RL2: LED5.2 U3.31 | length 1318.6
  Top Layer w20: LED5.2 2750,2490 3040,2780 3450,2780 3555,2885 U3.31
RL3: LED4.2 U3.32 | length 1224.6
  Top Layer w20: LED4.2 2815,3125 2975,2965 3763.79,2965 3783.79,2985 U3.32
RL4: LED6.2 U3.33 | length 1444.9
  Top Layer w20: LED6.2 2730,3785 3430,3085 U3.33
V_MEASURE: R8.2 R10.2 U3.8 | length 215.4
  Top Layer w20: R8.2 R10.2 4758.79,2510 4783.79,2485 U3.8
WIFI_ON: LED2.2 U3.35 | length 618.2
  Top Layer w20: U3.35 4020,3510 LED2.2
pads on no net: IC4.7 Transf1.3 Transf1.5 Transf1.7 Transf1.8 Transf1.9 U3.2 U3.3 U3.4 U3.5 U3.6 U3.9 U3.10 U3.11 U3.12 U3.13 U3.15 U3.16 U3.17 U3.18 U3.21 U3.23 U3.24 U3.27 U3.28 U3.29 U3.34 U3.36 U3.37 U3.38
copper on no net:
  other v4: 3171,2577
  other v5: 3172,2870

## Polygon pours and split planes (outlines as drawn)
GND_DC on Top Layer "100" (solid, pour order 4): 3821.67,4974.22 4956.67,4974.22 4956.67,1509.22 4951.67,1514.22 2771.67,1514.22 2771.67,3189.22 3681.67,3189.22 3681.67,3734.22 3821.67,3734.22
GND_DC on Top Layer "100" (solid, pour order 3): 2760,2352.5 2757.5,2350 2385,2350 2385,1515 2760,1515
+5 on Top Layer "100" (solid, pour order 1): 4550,4275 4620,4275 4620,4190 4550,4190
NetC5_1 on Top Layer "NETC5_1_L01_P000" (solid, pour order 0): 4650,4275 4720,4275 4720,4190 4650,4190
GND_DC on Bottom Layer "100" (solid, pour order 2): 3810,4975 4945,4975 4945,1510 4940,1515 2760,1515 2760,3190 3670,3190 3670,3735 3810,3735
GND_DC on Bottom Layer "100" (solid, pour order 5): 2761.2,2351.37 2758.7,2348.87 2386.2,2348.87 2386.2,1513.87 2761.2,1513.87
